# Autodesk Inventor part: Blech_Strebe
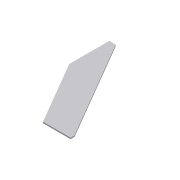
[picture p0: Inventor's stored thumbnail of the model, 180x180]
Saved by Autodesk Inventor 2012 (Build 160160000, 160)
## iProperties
Company: CAD-Verlag
Created: 2004-09
Part Number: Blech_Strebe
Document SubType Name: Modeling
Designer: Greiling
Manufacturer: Standard
Standards Organization: Custom
Density: 1 g/cm^3
Checked By: Jürgen Kronas
Stock Number: 10-10002
Material: Standard
Author: Juergen Kronas
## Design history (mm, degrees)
sketch "Skizze1"
  geometry: L1 (0, 480)-(0, -80) reference; L2 (-50, 0)-(300, 0) reference; L3 (-50, 0)-(300, 0) reference; L4 (0, -80)-(0, 480) reference; L5 (142.941, 0)-(250, 0); L6 (250, 0)-(250, 15); L7 (25, 400)-(0, 400); L8 (0, 400)-(0, 244.588); L9 (25, 400)-(250, 15); L10 (0, 244.588)-(142.941, 0)
  constraints: 12 end point, 3 parallel, 1 horizontal, 1 perpendicular
  dimensions: "d0" = 25 distance from line of L7.start L8; "d1" = 100 distance between parallel lines of L9 L10; "d2" = 400 distance between parallel lines of L7 L5; "d3" = 15 distance of L5.end L6.end; "d4" = 250 distance between parallel lines of L6 L8; "d5" = 0 distance between parallel lines of L5 L2
extrude "Extrusion1" new body sketch "Skizze1" distance "d6" = 5; taper "d7" = 0 deg
node "Volumenkörper1"
node "Volumenkörpern"
node "Oberflächenkörpern"
